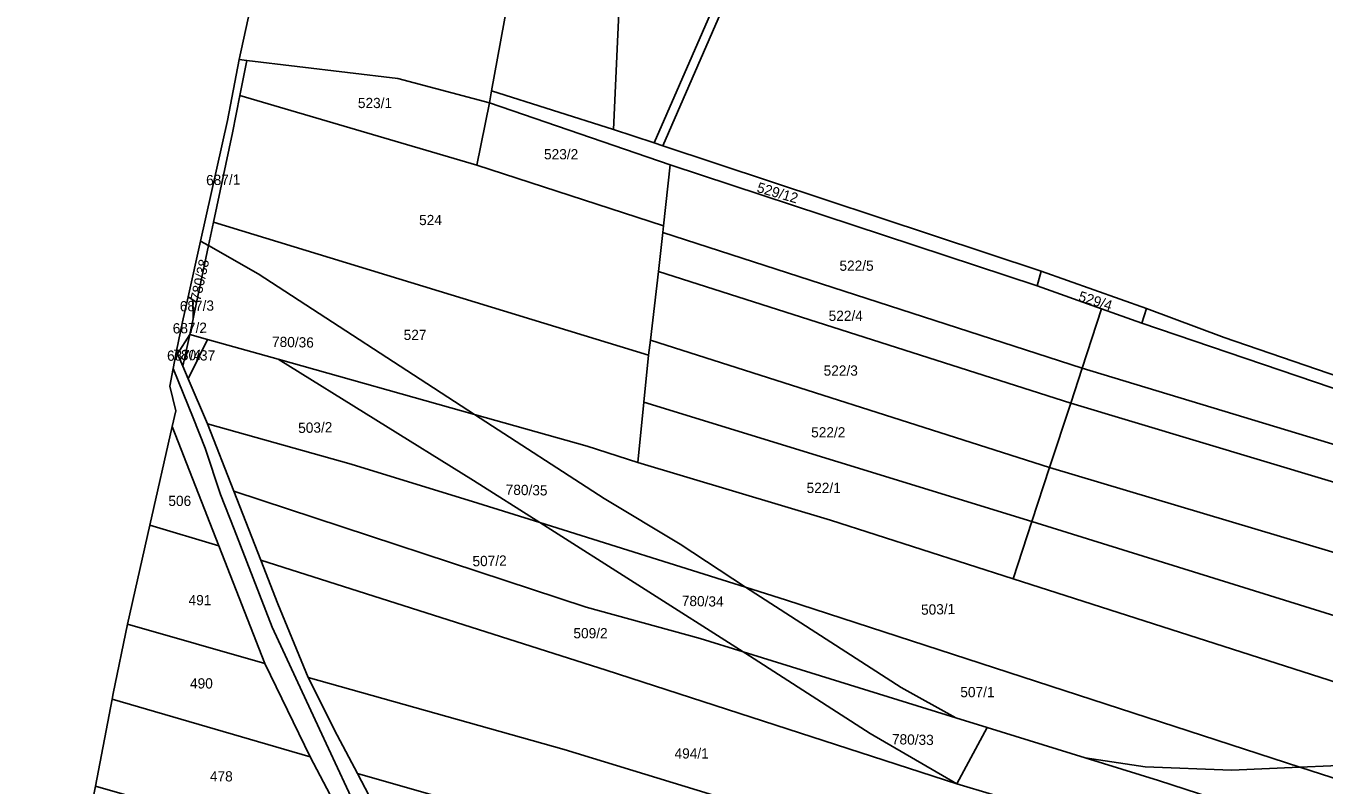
# Model space of a CAD drawing. Extents: x -629983 to -626385, y -1072828 to -1067897.
# Drawn here: x -627903.4 to -627522.6, y -1069773.1 to -1069550.4 of the extents above; entities that cross this region are included whole.
import ezdxf

# ---------------------------------------------------------------- set-up
doc = ezdxf.new("R2010")
doc.units = 0
for name, color, linetype in [('Parcela nároku', 7, 'Continuous'), ('Parcelní číslo', 7, 'Continuous'), ('Plocha PÚ', 7, 'Continuous'), ('Převzatý obvod_Opočno', 7, 'Continuous'), ('silnice III třídy', 7, 'Continuous')]:
    doc.layers.add(name, color=color, linetype=linetype)

msp = doc.modelspace()

# ---------------------------------------------------------------- linework, layer by layer
at = {"layer": 'Parcela nároku'}
for points in [[(-627829.14, -1069506.38), (-627840.86, -1069560.25), (-627838.63, -1069560.46), (-627794.31, -1069565.81), (-627767.42, -1069572.88), (-627766.78, -1069569.38), (-627756.76, -1069514.46), (-627775.13, -1069509.21), (-627772.67, -1069446.6), (-627769.72, -1069410.4), (-627759.48, -1069357.61), (-627738.4, -1069312.13), (-627721.03, -1069283.43), (-627732.73, -1069272.86), (-627742.48, -1069288.93), (-627754.94, -1069311.74), (-627767.18, -1069334.28), (-627781.05, -1069361.9), (-627787.25, -1069374.64), (-627795.42, -1069394.51), (-627801.9, -1069411.02), (-627805.08, -1069419.45), (-627809.45, -1069435.93), (-627817.47, -1069464.72)], [(-627756.76, -1069514.46), (-627766.78, -1069569.38), (-627731.06, -1069580.72), (-627727.3, -1069499.18), (-627725.05, -1069435.63), (-627758.81, -1069416.03), (-627769.72, -1069410.4), (-627772.67, -1069446.6), (-627775.13, -1069509.21)], [(-627387.95, -1069506.5), (-627392.29, -1069497.12), (-627417.27, -1069492.05), (-627450.43, -1069478.79), (-627532.45, -1069447.67), (-627584.07, -1069415.57), (-627619.46, -1069497.12), (-627666.16, -1069469.88), (-627716.51, -1069585.55), (-627605.55, -1069622.32), (-627574.69, -1069633.25), (-627551.87, -1069641.76), (-627517.96, -1069653.42), (-627480.65, -1069548.74), (-627453.72, -1069486.59), (-627426.1, -1069499.39)], [(-627731.06, -1069580.72), (-627727.3, -1069499.18), (-627725.05, -1069435.63), (-627668.46, -1069468.54), (-627719.14, -1069584.68)], [(-627668.46, -1069468.54), (-627666.16, -1069469.88), (-627716.51, -1069585.55), (-627719.14, -1069584.68)], [(-627838.63, -1069560.46), (-627840.86, -1069560.25), (-627844.31, -1069578.14), (-627852.19, -1069613.48), (-627849.83, -1069614.82), (-627848.37, -1069607.94), (-627842.8, -1069581.75), (-627840.65, -1069570.77)], [(-627838.63, -1069560.46), (-627794.31, -1069565.81), (-627767.42, -1069572.88), (-627771.13, -1069591.2), (-627840.65, -1069570.77)], [(-627766.78, -1069569.38), (-627767.42, -1069572.88), (-627714.44, -1069591.11), (-627606.71, -1069626.6), (-627605.55, -1069622.32), (-627716.51, -1069585.55), (-627719.14, -1069584.68), (-627731.06, -1069580.72)], [(-627840.65, -1069570.77), (-627771.13, -1069591.2), (-627716.38, -1069609.03), (-627716.59, -1069610.99), (-627717.82, -1069622.39), (-627720.21, -1069642.54), (-627720.73, -1069646.95), (-627848.37, -1069607.94), (-627842.8, -1069581.75)], [(-627767.42, -1069572.88), (-627771.13, -1069591.2), (-627716.38, -1069609.03), (-627714.44, -1069591.11)], [(-627714.44, -1069591.11), (-627716.38, -1069609.03), (-627716.59, -1069610.99), (-627593.56, -1069650.77), (-627587.87, -1069633.36), (-627606.71, -1069626.6)], [(-627848.37, -1069607.94), (-627720.73, -1069646.95), (-627722.11, -1069660.72), (-627723.89, -1069678.4), (-627738.75, -1069673.66), (-627771.83, -1069664.35), (-627835.29, -1069623.06), (-627849.83, -1069614.82)], [(-627716.59, -1069610.99), (-627593.56, -1069650.77), (-627596.9, -1069661), (-627717.82, -1069622.39)], [(-627852.19, -1069613.48), (-627855.83, -1069629.8), (-627854.5, -1069630.72), (-627853.37, -1069631.5), (-627849.83, -1069614.82)], [(-627853.37, -1069631.5), (-627854.38, -1069636.25), (-627855.36, -1069640.86), (-627850.1, -1069642.34), (-627829.37, -1069648.17), (-627771.83, -1069664.35), (-627835.29, -1069623.06), (-627849.83, -1069614.82)], [(-627717.82, -1069622.39), (-627720.21, -1069642.54), (-627603.09, -1069679.95), (-627596.9, -1069661)], [(-627605.55, -1069622.32), (-627574.69, -1069633.25), (-627575.98, -1069637.59), (-627587.87, -1069633.36), (-627606.71, -1069626.6)], [(-627854.38, -1069636.25), (-627854.5, -1069630.72), (-627855.83, -1069629.8), (-627857.48, -1069637.18), (-627859.28, -1069645.69), (-627858.91, -1069646.56), (-627855.36, -1069640.86)], [(-627854.5, -1069630.72), (-627853.37, -1069631.5), (-627854.38, -1069636.25)], [(-627587.87, -1069633.36), (-627593.56, -1069650.77), (-627407.04, -1069707.27), (-627403.61, -1069696.15), (-627575.98, -1069637.59)], [(-627574.69, -1069633.25), (-627575.98, -1069637.59), (-627403.61, -1069696.15), (-627328.11, -1069722.69), (-627328.29, -1069719.12), (-627358.86, -1069708.13), (-627413.18, -1069688.87), (-627469.84, -1069669.97), (-627517.96, -1069653.42), (-627551.87, -1069641.76)], [(-627858.91, -1069646.56), (-627855.36, -1069640.86), (-627857.35, -1069650.22)], [(-627855.36, -1069640.86), (-627857.35, -1069650.22), (-627855.78, -1069653.92), (-627850.1, -1069642.34)], [(-627850.1, -1069642.34), (-627829.37, -1069648.17), (-627772.09, -1069683.71), (-627752.67, -1069696.07), (-627770.8, -1069690.36), (-627807.95, -1069678.93), (-627850.19, -1069667.06), (-627855.78, -1069653.92)], [(-627720.21, -1069642.54), (-627720.73, -1069646.95), (-627722.11, -1069660.72), (-627608.26, -1069695.76), (-627603.09, -1069679.95)], [(-627857.35, -1069650.22), (-627855.78, -1069653.92), (-627850.19, -1069667.06), (-627842.45, -1069686.82), (-627834.52, -1069707.09), (-627829.49, -1069719.93), (-627820.6, -1069741.5), (-627812.09, -1069758.39), (-627806.17, -1069769.69), (-627790.22, -1069800.15), (-627788.86, -1069802.75), (-627799.63, -1069803.59), (-627803.52, -1069796.21), (-627820.06, -1069764.8), (-627833.28, -1069737.45), (-627846.8, -1069702.88), (-627860.49, -1069667.87), (-627859.45, -1069663.28), (-627861.21, -1069656.03), (-627859.28, -1069645.69), (-627858.91, -1069646.56)], [(-627733.78, -1069689.03), (-627711.43, -1069702.35), (-627692.33, -1069715.06), (-627752.67, -1069696.07), (-627772.09, -1069683.71), (-627829.37, -1069648.17), (-627771.83, -1069664.35)], [(-627596.9, -1069661), (-627593.56, -1069650.77), (-627407.04, -1069707.27), (-627410.1, -1069717.21)], [(-627722.11, -1069660.72), (-627723.89, -1069678.4), (-627667.39, -1069695.31), (-627613.74, -1069712.54), (-627608.26, -1069695.76)], [(-627596.9, -1069661), (-627410.1, -1069717.21), (-627415.84, -1069735.86), (-627603.09, -1069679.95)], [(-627738.75, -1069673.66), (-627723.89, -1069678.4), (-627667.39, -1069695.31), (-627613.74, -1069712.54), (-627456.74, -1069762.91), (-627511.5, -1069767.01), (-627529.71, -1069767.79), (-627680.28, -1069718.85), (-627692.33, -1069715.06), (-627711.43, -1069702.35), (-627733.78, -1069689.03), (-627771.83, -1069664.35)], [(-627860.49, -1069667.87), (-627867.04, -1069696.78), (-627846.8, -1069702.88)], [(-627807.95, -1069678.93), (-627850.19, -1069667.06), (-627842.45, -1069686.82), (-627739.04, -1069720.84), (-627705.65, -1069730.11), (-627693.02, -1069734.02), (-627752.67, -1069696.07), (-627770.8, -1069690.36)], [(-627603.09, -1069679.95), (-627415.84, -1069735.86), (-627421.4, -1069753.89), (-627608.26, -1069695.76)], [(-627705.65, -1069730.11), (-627693.02, -1069734.02), (-627691.16, -1069735.2), (-627655.76, -1069757.98), (-627630.31, -1069772.69), (-627733.19, -1069739.35), (-627834.52, -1069707.09), (-627842.45, -1069686.82), (-627739.04, -1069720.84)], [(-627608.26, -1069695.76), (-627421.4, -1069753.89), (-627423.59, -1069760.99), (-627456.74, -1069762.91), (-627613.74, -1069712.54)], [(-627867.04, -1069696.78), (-627846.8, -1069702.88), (-627833.28, -1069737.45), (-627873.63, -1069725.85)], [(-627646.64, -1069744.46), (-627630.63, -1069753.33), (-627693.02, -1069734.02), (-627752.67, -1069696.07), (-627692.33, -1069715.06)], [(-627608.8, -1069786.59), (-627609.39, -1069778.98), (-627630.31, -1069772.69), (-627733.19, -1069739.35), (-627834.52, -1069707.09), (-627829.49, -1069719.93), (-627820.6, -1069741.5), (-627745.48, -1069762.63), (-627686.33, -1069780.69), (-627646.23, -1069789.8), (-627638.29, -1069789.15), (-627625.96, -1069787.73)], [(-627529.71, -1069767.79), (-627680.28, -1069718.85), (-627692.33, -1069715.06), (-627646.64, -1069744.46), (-627630.63, -1069753.33), (-627621.4, -1069756.19), (-627592.68, -1069765.08), (-627575.06, -1069767.73), (-627549.72, -1069768.66)], [(-627873.63, -1069725.85), (-627877.84, -1069746.18), (-627878.16, -1069747.85), (-627820.06, -1069764.8), (-627833.28, -1069737.45)], [(-627693.02, -1069734.02), (-627630.63, -1069753.33), (-627621.4, -1069756.19), (-627630.31, -1069772.69), (-627655.76, -1069757.98), (-627691.16, -1069735.2)], [(-627820.6, -1069741.5), (-627745.48, -1069762.63), (-627686.33, -1069780.69), (-627646.23, -1069789.8), (-627715.85, -1069795.54), (-627806.17, -1069769.69), (-627812.09, -1069758.39)], [(-627878.16, -1069747.85), (-627820.06, -1069764.8), (-627803.52, -1069796.21), (-627883.02, -1069773.44)], [(-627592.68, -1069765.08), (-627571.1, -1069771.76), (-627473.63, -1069803.45), (-627402.13, -1069826.51), (-627407.04, -1069839.15), (-627451.84, -1069826.36), (-627609.39, -1069778.98), (-627630.31, -1069772.69), (-627621.4, -1069756.19)], [(-627456.74, -1069762.91), (-627427.11, -1069772.42), (-627386.63, -1069784.81), (-627395.97, -1069810.65), (-627508.19, -1069774.79), (-627529.71, -1069767.79), (-627511.5, -1069767.01)], [(-627575.06, -1069767.73), (-627549.72, -1069768.66), (-627529.71, -1069767.79), (-627508.19, -1069774.79), (-627395.97, -1069810.65), (-627402.13, -1069826.51), (-627473.63, -1069803.45), (-627571.1, -1069771.76), (-627592.68, -1069765.08)], [(-627715.85, -1069795.54), (-627806.17, -1069769.69), (-627790.22, -1069800.15), (-627783.15, -1069802.03), (-627761.23, -1069799.45)]]:
    msp.add_lwpolyline(points, close=True, dxfattribs=at)
at = {"layer": 'Plocha PÚ'}
msp.add_lwpolyline([(-627829.14, -1069506.38), (-627840.86, -1069560.25), (-627844.31, -1069578.14), (-627852.19, -1069613.48), (-627855.83, -1069629.8), (-627857.48, -1069637.18), (-627859.28, -1069645.69), (-627861.21, -1069656.03), (-627859.45, -1069663.28), (-627860.49, -1069667.87), (-627867.04, -1069696.78), (-627873.63, -1069725.85), (-627877.84, -1069746.18), (-627878.16, -1069747.85), (-627883.02, -1069773.44)], dxfattribs=at)
at = {"layer": 'Převzatý obvod_Opočno'}
msp.add_lwpolyline([(-627829.14, -1069506.38), (-627840.86, -1069560.25), (-627844.31, -1069578.14), (-627852.19, -1069613.48), (-627855.83, -1069629.8), (-627857.48, -1069637.18), (-627859.28, -1069645.69), (-627861.21, -1069656.03), (-627859.45, -1069663.28), (-627860.49, -1069667.87), (-627867.04, -1069696.78), (-627873.63, -1069725.85), (-627877.84, -1069746.18), (-627878.16, -1069747.85), (-627883.02, -1069773.44), (-627888.14, -1069798.48), (-627891.24, -1069813.67), (-627892.92, -1069821.87), (-627897.73, -1069844.57), (-627901.61, -1069862.41), (-627902.33, -1069865.35), (-627903.41, -1069869.77)], dxfattribs=at)
at = {"layer": 'silnice III třídy'}
msp.add_lwpolyline([(-627794.24, -1069803.17), (-627806.73, -1069779.37), (-627817.28, -1069756.67), (-627831.17, -1069726.78), (-627842.34, -1069697.99), (-627846.29, -1069687.82), (-627850.8, -1069674.22), (-627854.36, -1069665.33), (-627860.24, -1069650.86)], dxfattribs=at)

# ---------------------------------------------------------------- texts
at = {"layer": 'Parcelní číslo'}
for s, p in [('523/1', (-627806.02, -1069574.46)), ('523/2', (-627751.42, -1069589.5)), ('524', (-627788.07, -1069608.8)), ('522/5', (-627664.74, -1069622.2)), ('522/4', (-627667.91, -1069636.9)), ('527', (-627792.6, -1069642.5)), ('522/3', (-627669.38, -1069652.97)), ('522/2', (-627673.04, -1069671.08)), ('522/1', (-627674.38, -1069687.39)), ('506', (-627861.63, -1069691.19)), ('491', (-627855.7, -1069720.31)), ('509/2', (-627742.79, -1069730.01)), ('490', (-627855.28, -1069744.74)), ('507/1', (-627629.28, -1069747.3)), ('494/1', (-627713.12, -1069765.3)), ('478', (-627849.44, -1069772.01))]:
    msp.add_text(s, height=3, dxfattribs=at).set_placement(p)
for s, rotation, p in [('687/1', 1.3178, (-627850.52, -1069597.11)), ('529/12', 343.7993, (-627689.19, -1069599.03)), ('780/38', 77.5785, (-627852.26, -1069631.2)), ('687/3', 1.3178, (-627858.24, -1069634.11)), ('529/4', 342.4381, (-627594.86, -1069630.93)), ('687/2', 1.3178, (-627860.31, -1069640.6)), ('780/36', 358.7862, (-627831.25, -1069644.49)), ('687/4', 1.3178, (-627861.98, -1069648.62)), ('780/37', 358.7862, (-627860.2, -1069648.32)), ('503/2', 1.3178, (-627823.51, -1069669.8)), ('780/35', 358.7862, (-627762.69, -1069687.88)), ('507/2', 1.3178, (-627772.37, -1069708.91)), ('780/34', 358.7862, (-627711.02, -1069720.5)), ('503/1', 1.3178, (-627640.77, -1069723.13)), ('780/33', 358.7862, (-627649.37, -1069761.09))]:
    msp.add_text(s, height=3, rotation=rotation, dxfattribs=at).set_placement(p)

doc.saveas('drawing.dxf')
